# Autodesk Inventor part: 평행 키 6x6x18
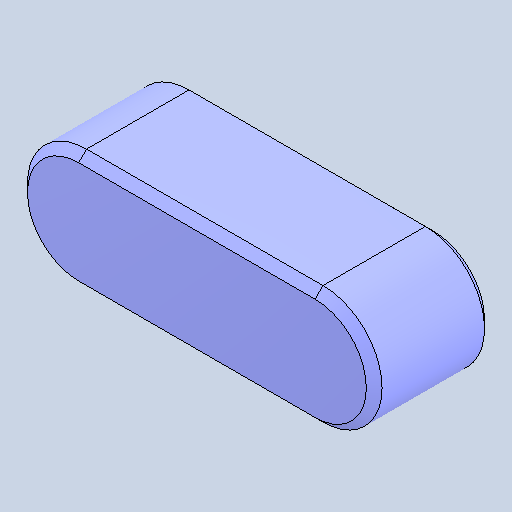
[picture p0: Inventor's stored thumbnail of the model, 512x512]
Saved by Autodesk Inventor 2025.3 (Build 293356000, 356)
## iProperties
Created: 2026-01
Part Number: 평행 키 6x6x18
Material: 강철, 연강
Description: 키 및 해당 키홈
Document SubType Name: Modeling
Designer: pc6
Density: 7.85 g/cm^3
Appearance: 기본값
Author: jhkim
Sending System: Autodesk Inventor 2026
Preprocessor: ST-DEVELOPER v20.1
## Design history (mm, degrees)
feature "Solid1"
node "솔리드1"
